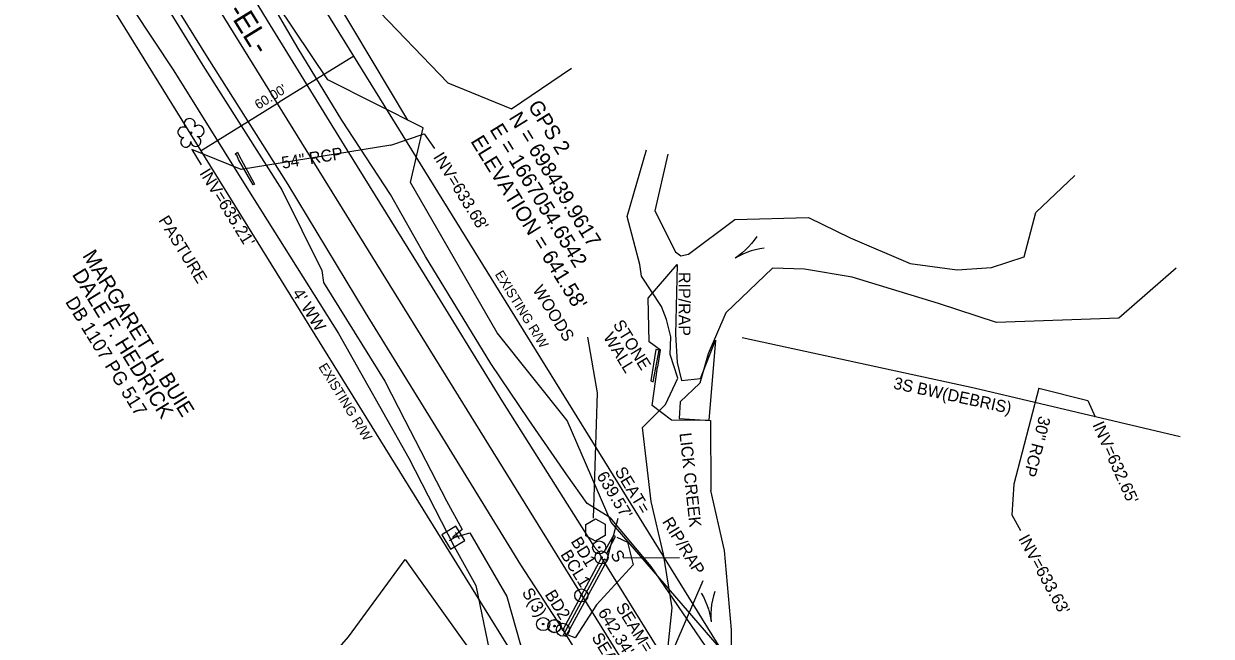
# Model space of a CAD drawing. Extents: x 1666477 to 1667385, y 697735 to 699095.
# Drawn here: x 1666863.7 to 1667260.3, y 698404.4 to 698609.2 of the extents above; entities that cross this region are included whole.
import ezdxf

# ---------------------------------------------------------------- set-up
doc = ezdxf.new("R2010")
doc.units = 0
for name, color, linetype in [('CTL Supplemental Horizontal and Vertical Leader', 7, 'Continuous'), ('CTL Supplemental Horizontal and Vertical Text', 7, 'Continuous'), ('Exist Horizontal Alignment', 7, 'Continuous'), ('Exist Horizontal Alignment Direction Label', 7, 'Continuous'), ('Exist Hydro Stream Flow Arrow CELL', 7, 'Continuous'), ('Exist Hydro Stream or Body of Water', 7, 'Continuous'), ('Exist Hydro Stream or Body of Water Text', 7, 'Continuous'), ('Exist Other Culture Area Outline', 7, 'Continuous'), ('Exist Other Culture Area Outline Leader', 7, 'Continuous'), ('Exist Other Culture Area Outline Text', 7, 'Continuous'), ('Exist Other Culture Fence Line', 7, 'Continuous'), ('Exist Other Culture Fence Line Text', 7, 'Continuous'), ('Exist Other Culture Located Object CELL', 7, 'Continuous'), ('Exist Other Culture Located Object Leader', 7, 'Continuous'), ('Exist Other Culture Located Object Text', 7, 'Continuous'), ('Exist Other Culture Sign CELL', 7, 'Continuous'), ('Exist Other Culture Sign Text', 7, 'Continuous'), ('Exist Property Deed Book Text', 7, 'Continuous'), ('Exist Property Line Text', 7, 'Continuous'), ('Exist Property Owner Text', 7, 'Continuous'), ('Exist Right of Way Line', 7, 'Continuous'), ('Exist Right of Way Line Text', 7, 'Continuous'), ('Exist Right of Way Width CELL', 7, 'Continuous'), ('Exist Roads EOP', 7, 'Continuous'), ('Exist Roads EOP Other', 7, 'Continuous'), ('Exist Structure Major Bridge Seat Top Elevation', 7, 'Continuous'), ('Exist Structure Major Deck Tunnel Box Culvert', 7, 'Continuous'), ('Exist Structure Minor Head and End Wall', 7, 'Continuous'), ('Exist Structure Minor Pipes RCP 30 Inch', 7, 'Continuous'), ('Exist Structure Minor Pipes RCP 30 Inch Invert', 7, 'Continuous'), ('Exist Structure Minor Pipes RCP 30 Inch Leader', 7, 'Continuous'), ('Exist Structure Minor Pipes RCP 30 Inch Text', 7, 'Continuous'), ('Exist Structure Minor Pipes RCP 54 Inch', 7, 'Continuous'), ('Exist Structure Minor Pipes RCP 54 Inch Invert', 7, 'Continuous'), ('Exist Structure Minor Pipes RCP 54 Inch Leader', 7, 'Continuous'), ('Exist Structure Minor Pipes RCP 54 Inch Text', 7, 'Continuous'), ('Exist Utilities Telephone Pedestal CELL', 7, 'Continuous'), ('Exist Utilities Telephone UG Cable SUE LOS C', 7, 'Continuous'), ('Exist Utilities Water UG Line SUE LOS C', 7, 'Continuous'), ('Exist Vegetation Tree CELL', 7, 'Continuous'), ('Exist Vegetation Woods Line', 7, 'Continuous'), ('Exist Vegetation Woods Line Text', 7, 'Continuous'), ('Raster_Level_0', 7, 'Continuous')]:
    doc.layers.add(name, color=color, linetype=linetype)

msp = doc.modelspace()

# ---------------------------------------------------------------- linework, layer by layer
at = {"layer": 'CTL Supplemental Horizontal and Vertical Leader'}
msp.add_lwpolyline([(1667053.97, 698443.96), (1667055.31, 698485.81), (1667052.08, 698504.41)], dxfattribs=at)
at = {"layer": 'Exist Horizontal Alignment'}
msp.add_line((1667148.23, 698259.58), (1666793.59, 698833.01), dxfattribs=at)
at = {"layer": 'Exist Hydro Stream Flow Arrow CELL'}
for p, q in [((1667105.52, 698533.5), (1667105.52, 698533.5)), ((1667092.77, 698414.16), (1667092.77, 698414.16))]:
    msp.add_line(p, q, dxfattribs=at)
for points in [[(1667108.54, 698538.1), (1667107.72, 698536.88), (1667106.76, 698535.73), (1667105.8, 698534.61), (1667104.77, 698533.59), (1667103.65, 698532.62), (1667102.48, 698531.69), (1667101.28, 698530.85)], [(1667110.97, 698534.23), (1667109.52, 698534.02), (1667108.06, 698533.66), (1667106.63, 698533.28), (1667105.27, 698532.79), (1667103.91, 698532.21), (1667102.56, 698531.56), (1667101.28, 698530.85)], [(1667089.94, 698418.88), (1667090.69, 698417.62), (1667091.31, 698416.25), (1667091.9, 698414.9), (1667092.36, 698413.53), (1667092.76, 698412.1), (1667093.09, 698410.64), (1667093.33, 698409.2)], [(1667094.49, 698419.39), (1667094.04, 698417.99), (1667093.74, 698416.52), (1667093.46, 698415.07), (1667093.31, 698413.63), (1667093.23, 698412.15), (1667093.24, 698410.66), (1667093.33, 698409.2)]]:
    msp.add_lwpolyline(points, dxfattribs=at)
at = {"layer": 'Exist Hydro Stream or Body of Water'}
for points in [[(1667070.42, 698474.24), (1667078.04, 698481.89), (1667082.18, 698490.75), (1667079.62, 698498.64), (1667079.86, 698504.51), (1667078.43, 698510.33), (1667076.71, 698514.74), (1667070.09, 698524.88), (1667069.53, 698528.73), (1667065.25, 698544.81), (1667071.74, 698567.11)], [(1667078.85, 698565.65), (1667074.49, 698546.71), (1667081.42, 698532.99), (1667083.13, 698531.68), (1667085.73, 698532.24), (1667101.18, 698543.78), (1667125.77, 698544.41), (1667139.74, 698537.68), (1667159.77, 698529.05), (1667175.5, 698526.97), (1667186.94, 698527.74), (1667197.91, 698531.34), (1667201.74, 698546.16), (1667214.77, 698558.52)], [(1667248.67, 698527.53), (1667229.49, 698510.79), (1667188.63, 698509.34), (1667169.29, 698515.66), (1667140.38, 698524.51), (1667124.48, 698527.17), (1667113.75, 698527.51), (1667098.2, 698512.57), (1667092.25, 698498.81), (1667089.5, 698489.11), (1667082.96, 698482.82), (1667082.67, 698477.2), (1667093.12, 698476.62), (1667093.24, 698453.17)], [(1667076.6, 698397.25), (1667078.86, 698399.96), (1667080.25, 698413.94), (1667077.42, 698431.91), (1667073.29, 698449.49), (1667070.42, 698474.24)], [(1667095.23, 698373.57), (1667100.07, 698395.14), (1667100.11, 698406.62), (1667097.77, 698433.13), (1667093.24, 698453.17)]]:
    msp.add_lwpolyline(points, dxfattribs=at)
at = {"layer": 'Exist Other Culture Area Outline'}
for points in [[(1667092.53, 698476.55), (1667080.04, 698476.71), (1667073.58, 698481.54), (1667075.36, 698494.36), (1667075.46, 698494.41), (1667076.35, 698500.09), (1667072.58, 698502.88), (1667072.25, 698517.46), (1667081.91, 698528.7), (1667081.35, 698505.35), (1667081.91, 698495.99), (1667083.38, 698490), (1667089.78, 698490.62), (1667094.75, 698503.4), (1667092.53, 698476.55)], [(1667075.91, 698500.04), (1667074.77, 698500.31), (1667073.1, 698489.82), (1667073.94, 698489.52), (1667075.91, 698500.04)], [(1667061.75, 698437.57), (1667065.33, 698435.91), (1667067.24, 698428.27), (1667054.98, 698414.94), (1667047.85, 698403.88), (1667045.49, 698404.83)]]:
    msp.add_lwpolyline(points, dxfattribs=at)
at = {"layer": 'Exist Other Culture Area Outline Leader'}
msp.add_line((1667063.89, 698430.67), (1667082.72, 698430.8), dxfattribs=at)
at = {"layer": 'Exist Other Culture Fence Line'}
msp.add_line((1666926.39, 698686.64), (1666991.9, 698577.03), dxfattribs=at)
for points in [[(1666763.48, 698666.33), (1666797.8, 698665.64), (1666797.79, 698665.65), (1666848.77, 698658.33), (1666867.75, 698656.95), (1666879.42, 698645.59), (1666913.77, 698593.47), (1666938.8, 698553.46), (1666968.81, 698505.62), (1666992.27, 698464), (1667007.43, 698434.44)], [(1667103.67, 698504.31), (1667181.12, 698487.51), (1667249.94, 698471.22)], [(1667007.43, 698434.44), (1667014.74, 698421.43), (1667019.24, 698399.28), (1667010.17, 698384.16), (1666992.08, 698354.68), (1666978.35, 698332.72)]]:
    msp.add_lwpolyline(points, dxfattribs=at)
at = {"layer": 'Exist Other Culture Located Object CELL'}
for centre, radius in [((1667056.7, 698430.78), 2.18), ((1667056.7, 698430.78), 0.24), ((1667049.94, 698418.08), 2.18), ((1667049.94, 698418.08), 0.24), ((1667043.8, 698406.61), 2.18), ((1667043.8, 698406.61), 0.24)]:
    msp.add_circle(centre, radius, dxfattribs=at)
at = {"layer": 'Exist Other Culture Located Object Leader'}
msp.add_line((1667058.44, 698429.64), (1667062.29, 698443.86), dxfattribs=at)
at = {"layer": 'Exist Other Culture Sign CELL'}
for centre, radius in [((1667055.9, 698434.13), 2.18), ((1667055.9, 698434.13), 0.24), ((1667037.19, 698408.48), 2.18), ((1667037.19, 698408.48), 0.24), ((1667040.91, 698407.78), 2.18), ((1667041, 698407.84), 2.18), ((1667041, 698407.84), 0.24), ((1667040.91, 698407.78), 0.24)]:
    msp.add_circle(centre, radius, dxfattribs=at)
at = {"layer": 'Exist Property Line Text'}
msp.add_line((1667090.57, 698422.99), (1666987.08, 698184.48), dxfattribs=at)
at = {"layer": 'Exist Right of Way Line'}
for p, q in [((1667122.72, 698243.8), (1666768.07, 698817.23)), ((1667173.75, 698275.36), (1666882.65, 698746.04))]:
    msp.add_line(p, q, dxfattribs=at)
at = {"layer": 'Exist Right of Way Width CELL'}
for p in [(1666973.96, 698598.4), (1666922.93, 698566.84)]:
    msp.add_line(p, (1666949.02, 698582.97), dxfattribs=at)
at = {"layer": 'Exist Roads EOP'}
for points in [[(1666870.75, 698733.33), (1666877.61, 698720.31), (1666893.3, 698694.61), (1666919.49, 698652.35), (1666945, 698610.31), (1666971.56, 698567.04), (1666997.43, 698525.34), (1667023.64, 698482.78), (1667049.97, 698441.03), (1667054.17, 698434.34), (1667055.97, 698432.32), (1667056, 698431.95), (1667056.6, 698430.99)], [(1666880.47, 698669.55), (1666899.28, 698639.61), (1666924.98, 698598.12), (1666951.86, 698555.5), (1666977.68, 698512.7), (1667003.52, 698470.73), (1667029.64, 698428.31), (1667043.53, 698406.89), (1667043.73, 698406.63)]]:
    msp.add_lwpolyline(points, dxfattribs=at)
at = {"layer": 'Exist Roads EOP Other'}
for points in [[(1667058.48, 698432.23), (1667060.32, 698435.93), (1667061.31, 698437.79), (1667060.71, 698438.12), (1667059.61, 698436.2), (1667057.92, 698433.16)], [(1667057.6, 698430.26), (1667056.32, 698427.89), (1667044.66, 698406.21), (1667043.92, 698404.84), (1667044.81, 698404.42), (1667045.56, 698405.77), (1667057.26, 698427.36), (1667058.44, 698429.64), (1667057.6, 698430.26)]]:
    msp.add_lwpolyline(points, dxfattribs=at)
at = {"layer": 'Exist Structure Major Deck Tunnel Box Culvert'}
msp.add_lwpolyline([(1667043.8, 698406.61), (1667099.17, 698316.6), (1667112.38, 698340.95), (1667056.7, 698430.78)], close=True, dxfattribs=at)
at = {"layer": 'Exist Structure Minor Head and End Wall'}
msp.add_lwpolyline([(1666940.76, 698555.56), (1666940.3, 698555.42), (1666939.51, 698556.71), (1666935.4, 698563.89), (1666934.93, 698565.06), (1666934.3, 698565.66), (1666935.1, 698566.32), (1666935.54, 698565.25), (1666939.92, 698557.27), (1666940.76, 698555.56)], dxfattribs=at)
at = {"layer": 'Exist Structure Minor Pipes RCP 30 Inch'}
msp.add_line((1667202.75, 698487.37), (1667194.36, 698455.28), dxfattribs=at)
at = {"layer": 'Exist Structure Minor Pipes RCP 30 Inch Leader'}
for points in [[(1667202.75, 698487.37), (1667219.14, 698483.29), (1667221.59, 698477.81)], [(1667194.36, 698455.28), (1667193.72, 698445.05), (1667196.59, 698439.79)]]:
    msp.add_lwpolyline(points, dxfattribs=at)
at = {"layer": 'Exist Structure Minor Pipes RCP 54 Inch'}
msp.add_line((1666986.29, 698568.67), (1666936.26, 698560.51), dxfattribs=at)
at = {"layer": 'Exist Structure Minor Pipes RCP 54 Inch Leader'}
for points in [[(1666986.29, 698568.67), (1666997.41, 698572.42), (1667000.84, 698567.49)], [(1666936.26, 698560.51), (1666919.84, 698567.17), (1666922.94, 698562.03)]]:
    msp.add_lwpolyline(points, dxfattribs=at)
at = {"layer": 'Exist Utilities Telephone Pedestal CELL'}
msp.add_line((1667007.12, 698437.48), (1667007.12, 698437.48), dxfattribs=at)
msp.add_lwpolyline([(1667003.29, 698438.31), (1667006.22, 698433.55), (1667010.98, 698436.49), (1667008.05, 698441.25), (1667003.29, 698438.31)], dxfattribs=at)
at = {"layer": 'Exist Utilities Telephone UG Cable SUE LOS C'}
for points in [[(1666879.11, 698652.82), (1666883.33, 698655.98), (1666884.9, 698655.82), (1666898.04, 698636.86), (1666923.51, 698595.3), (1666949.94, 698553.7), (1666963.27, 698526.7), (1666963.8, 698522.77), (1666984.35, 698489.78), (1666990.94, 698476.64), (1667004.92, 698449.71), (1667010.1, 698440.1), (1667007, 698437.59)], [(1667007.04, 698437.31), (1667012.69, 698439), (1667025.03, 698417.67), (1667029.64, 698401.58), (1667033.93, 698394.5)]]:
    msp.add_lwpolyline(points, dxfattribs=at)
at = {"layer": 'Exist Utilities Water UG Line SUE LOS C'}
for points in [[(1667059.41, 698444.14), (1667051.92, 698448.86), (1667045.14, 698458.4), (1667032.4, 698476.75), (1667019.73, 698495.63), (1666997.89, 698531.42), (1666986.24, 698552.11), (1666969.96, 698576.95), (1666955.37, 698600.92), (1666938.85, 698629.31), (1666923.47, 698654.27), (1666910.42, 698675.41), (1666884.79, 698661.27), (1666880.83, 698664.06), (1666873.43, 698666)], [(1667059.41, 698444.14), (1667073.1, 698427.72), (1667104.66, 698381.57), (1667117.42, 698358), (1667121.04, 698341.29), (1667125.32, 698333.24), (1667131.2, 698321.25), (1667138.45, 698308.78), (1667153.1, 698281.21), (1667169.96, 698252.92), (1667185.25, 698227.66), (1667201.73, 698200.17), (1667214.36, 698176.9), (1667224.64, 698159.82), (1667231.51, 698149.42), (1667241.64, 698140.85), (1667260.35, 698131.31)]]:
    msp.add_lwpolyline(points, dxfattribs=at)
at = {"layer": 'Exist Vegetation Tree CELL'}
msp.add_line((1666919.5, 698572.8), (1666919.5, 698572.8), dxfattribs=at)
msp.add_circle((1666919.5, 698572.8), 0.326, dxfattribs=at)
for centre, radius, start, end in [((1666916.89, 698572.96), 1.73, 62.6636, 279.3457), ((1666919.11, 698575.68), 1.86, 330.1651, 219.7134), ((1666922.05, 698573.39), 1.9, 257.1011, 134.1999), ((1666917.79, 698569.68), 1.69, 111.5671, 6.231), ((1666921.17, 698569.9), 1.7, 181.2822, 74.56)]:
    msp.add_arc(centre, radius, start, end, dxfattribs=at)
at = {"layer": 'Exist Vegetation Woods Line'}
for points in [[(1666997.11, 698574.49), (1666965.25, 698590.45), (1666948.43, 698615.52), (1666956.99, 698623.99), (1666979.86, 698615.98), (1667005.31, 698589.51), (1667026.65, 698580.74), (1667046.61, 698594.4)], [(1667118.69, 698374.52), (1667059.9, 698442.55), (1667045.2, 698476.62), (1667021.77, 698505.86), (1666992.92, 698556.21), (1666997.11, 698574.49)], [(1666949.35, 698377.99), (1666972.22, 698404.18), (1666991.07, 698430.12), (1667069.16, 698320.71), (1667098.04, 698295.65), (1667137.31, 698229.81), (1667095.15, 698211.88), (1667068.09, 698191.44)]]:
    msp.add_lwpolyline(points, dxfattribs=at)
at = {"layer": 'Raster_Level_0'}
msp.add_line((1667054.65, 698439.96), (1667054.65, 698439.96), dxfattribs=at)
msp.add_lwpolyline([(1667051.42, 698441.83), (1667054.67, 698443.65), (1667057.92, 698441.86), (1667057.87, 698438.13), (1667054.62, 698436.25), (1667051.42, 698438.06)], close=True, dxfattribs=at)

# ---------------------------------------------------------------- texts
at = {"layer": 'CTL Supplemental Horizontal and Vertical Text'}
for s, p in [('GPS 2', (1667031.92, 698581.78)), ('N = 698439.9617', (1667025.54, 698577.84)), ('E = 1667054.6542', (1667019.16, 698573.9)), ("ELEVATION = 641.58'", (1667012.78, 698569.96))]:
    msp.add_text(s, height=5, rotation=301.6959, dxfattribs=at).set_placement(p)
at = {"layer": 'Exist Horizontal Alignment Direction Label'}
msp.add_text('-EL-', height=7, rotation=301.6959, dxfattribs=at).set_placement((1666931.68, 698613.44))
at = {"layer": 'Exist Hydro Stream or Body of Water Text'}
msp.add_text('LICK CREEK', height=4, rotation=276.1748, dxfattribs=at).set_placement((1667082.69, 698472.29))
at = {"layer": 'Exist Other Culture Area Outline Text'}
for s, rotation, p in [('RIP/RAP', 270, (1667082.4, 698526.25)), ('STONE', 301.6959, (1667060.38, 698508.7)), ('WALL', 301.6959, (1667057.1, 698504.48)), ('RIP/RAP', 301.6959, (1667076.8, 698442.72))]:
    msp.add_text(s, height=4, rotation=rotation, dxfattribs=at).set_placement(p)
at = {"layer": 'Exist Other Culture Fence Line Text'}
for s, rotation, p in [("4' WW", 302.0967, (1666953.23, 698519.17)), ('3S BW(DEBRIS)', 347.7595, (1667153.93, 698487.27))]:
    msp.add_text(s, height=4, rotation=rotation, dxfattribs=at).set_placement(p)
at = {"layer": 'Exist Other Culture Located Object Text'}
for s, p in [('BD1', (1667046.29, 698436.14)), ('BCL1', (1667042.84, 698431.79)), ('BD2', (1667037.61, 698418.41))]:
    msp.add_text(s, height=4, rotation=301.6959, dxfattribs=at).set_placement(p)
at = {"layer": 'Exist Other Culture Sign Text'}
for s, p in [('S', (1667059.5, 698431.75)), ('S(3)', (1667029.94, 698419.06))]:
    msp.add_text(s, height=4, rotation=301.6959, dxfattribs=at).set_placement(p)
at = {"layer": 'Exist Property Deed Book Text'}
msp.add_text('DB 1107 PG 517', height=4.5, rotation=301.6959, dxfattribs=at).set_placement((1666877.41, 698516.27))
at = {"layer": 'Exist Property Owner Text'}
for s, p in [('MARGARET H. BUIE', (1666883.14, 698531.71)), ('DALE F. HEDRICK', (1666879.67, 698525.42))]:
    msp.add_text(s, height=5, rotation=301.6959, dxfattribs=at).set_placement(p)
at = {"layer": 'Exist Right of Way Line Text'}
for p in [(1667020.94, 698525.48), (1666962.02, 698494.51)]:
    msp.add_text('EXISTING R/W', height=3.2, rotation=301.7353, dxfattribs=at).set_placement(p)
at = {"layer": 'Exist Right of Way Width CELL'}
msp.add_text("60.00'", height=3.2, rotation=31.7353, dxfattribs=at).set_placement((1666942.07, 698580.46))
at = {"layer": 'Exist Structure Major Bridge Seat Top Elevation'}
for s, rotation, p in [('SEAT=', 301.05, (1667060.96, 698459.61)), ("639.57'", 301.05, (1667054.89, 698458.06)), ("642.34'", 301.6959, (1667055.32, 698412.38)), ('SEAM=', 301.6959, (1667061.27, 698414.16)), ('SEAM=', 301.6959, (1667053.22, 698404.08))]:
    msp.add_text(s, height=4, rotation=rotation, dxfattribs=at).set_placement(p)
at = {"layer": 'Exist Structure Minor Pipes RCP 30 Inch Invert'}
for s, rotation, p in [("INV=632.65'", 294.091, (1667220.58, 698475.17)), ("INV=633.63'", 298.6315, (1667195.79, 698437.07))]:
    msp.add_text(s, height=4, rotation=rotation, dxfattribs=at).set_placement(p)
at = {"layer": 'Exist Structure Minor Pipes RCP 30 Inch Text'}
msp.add_text('30" RCP', height=4, rotation=255.3482, dxfattribs=at).set_placement((1667202.9, 698478.32))
at = {"layer": 'Exist Structure Minor Pipes RCP 54 Inch Invert'}
for s, p in [("INV=633.68'", (1667000.34, 698564.71)), ("INV=635.21'", (1666922.26, 698559.29))]:
    msp.add_text(s, height=4, rotation=301.6959, dxfattribs=at).set_placement(p)
at = {"layer": 'Exist Structure Minor Pipes RCP 54 Inch Text'}
msp.add_text('54" RCP', height=4, rotation=9.2546, dxfattribs=at).set_placement((1666950.14, 698560.73))
at = {"layer": 'Exist Utilities Telephone Pedestal CELL'}
msp.add_text('T', height=3.42, rotation=301.6399, dxfattribs=at).set_placement((1667005.07, 698437.54))
at = {"layer": 'Exist Vegetation Woods Line Text'}
for s, p in [('PASTURE', (1666908.55, 698543.54)), ('WOODS', (1667033.52, 698520.29))]:
    msp.add_text(s, height=4, rotation=301.6959, dxfattribs=at).set_placement(p)

doc.saveas('drawing.dxf')
